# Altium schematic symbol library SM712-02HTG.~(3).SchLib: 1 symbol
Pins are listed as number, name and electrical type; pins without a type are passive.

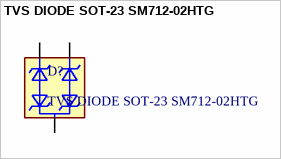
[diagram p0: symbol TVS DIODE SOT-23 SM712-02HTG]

## TVS DIODE SOT-23 SM712-02HTG
designator D?
TVS Diode, SM712 Series, 31V Clamp, 600W Peak Pulse, Surface Mount,Bi-Directional, SOT23-3 ¦ Littelfuse SM712-02HTG; MF: Littelfuse Inc.
footprint SOT23
pins: 1, 2, 3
